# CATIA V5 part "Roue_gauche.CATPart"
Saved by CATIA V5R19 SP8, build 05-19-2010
Part number: Roue_gauche
Bounding box of the stored display mesh (mm): x -1125 to -825, y 1050 to 1950, z -1299.802 to -400.198
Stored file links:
  G:\EU_thinkMotion\CFAO_2010\MMS_groupe2\MMS_groupe2\OK\mmartini\mmartiniCFAO\Roue_gauche.CATPart
  C:\Users\Mathieu Martini\Desktop\CFAO\Animation\CFAO.CATProduct
  G:\EU_thinkMotion\CFAO_2010\MMS_groupe2\MMS_groupe2\OK\mmartini\mmartiniCFAO\Squelette.CATPart
  G:\EU_thinkMotion\CFAO_2010\MMS_groupe2\MMS_groupe2\OK\mmartini\mmartiniCFAO\Roue_droite.CATPart
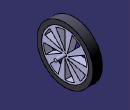
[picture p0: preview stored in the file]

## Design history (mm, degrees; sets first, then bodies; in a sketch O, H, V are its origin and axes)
Parameters
  LENGTH = 150 mm
External parameters (linked from other documents)
  External.diametre_canon = 150 mm
AxisSystem1: origin (0, 0, 0), X (1, 0, 0), Y (0, 1, 0), Z (0, 0, 1)
Set1
  Sketch1 on Plane1, origin (-975, 0, 0), H (0, 1, 0), V (0, 0, 1)
    circle A1 centre (1500, -850) radius 450
    point P1 (1500, -850)
    reference projected point E1 (1500, -850) from Line1
    reference intersected line E2 through (0, -1300) direction (-1, 0) from Plane2
    circle A2 centre (1500, -850) radius 375
    distance A2 A1 = 75 {= External.diametre_canon /2}
    coincidence: P1 E1
    tangency: A1 E2
Set2
  Plane1: linked copy from another document
  Line1 "axe_roue": linked copy from another document
  Plane2 "sol": linked copy from another document
Body1 (main body)
  Pad1: profile Sketch1, direction (-1, 0, 0), length 150 {= External.diametre_canon}
  Sketch2 on Plane1, origin (-975, 0, 0), H (0, 1, 0), V (0, 0, 1)
    projected circle E1 centre (1500, -850) radius 375 from edge [start face of Pad1 | face of Pad1 from Sketch1.A2]
  Pad2: profile Sketch2, direction (-1, 0, 0), length 120 {= External.diametre_canon -External.diametre_canon /5}
  Sketch3 on Plane1, origin (-975, 0, 0), H (0, 1, 0), V (0, 0, 1)
    axis line L1 (1500, -850) -> (1500, -390.9786)
    point P1 (1500, -850)
    reference projected point E1 (1500, -850)
    line L2 (1500, -505) -> (1500, -800)
    point P3 (1500, -505)
    point P4 (1500, -800)
    reference projected circle E2 centre (1500, -850) radius 375
    arc A1 centre (1500, -850) radius 345 from (1500, -505) to (1349.6041, -539.5067) ccw
    line L3 (1500, -800) -> (1349.6041, -539.5067)
    point P6 (1500, -505)
    distance E2 P3 = 30 {= LENGTH /5}
    distance P4 P1 = 50 {= LENGTH /3}
    angle L3 L2 = 30
    vertical: L1 V, L2 V
    coincidence: P1 E1, P4 L1, A1 P3, L1 P6, P3 P6
  Pocket1: profile Sketch3, direction (-1, 0, 0), up to end face of Pad2
  CircPattern1: of Pocket1, instances 8, angular step 45, axis from Line1
  Sketch4 on Plane1, origin (-975, 0, 0), H (0, 1, 0), V (0, 0, 1)
    projected circle E1 centre (1500, -850) radius 375 from edge [face of Pad1 from Sketch1.A2 | end face of Pad1]
  Pocket2: profile Sketch4, direction (-1, 0, 0), length 1.5 {= External.diametre_canon /100}
  Sketch5 on Plane1, origin (-975, 0, 0), H (0, 1, 0), V (0, 0, 1)
    circle A1 centre (1500, -850) radius 25
    point P1 (1500, -850)
    reference projected point E1 (1500, -850) from Line1
    radius A1 = 25 {= External.diametre_canon /6}
    coincidence: P1 E1
  Pad3: profile Sketch5, direction (1, 0, 0), length 150 {= External.diametre_canon}, opposite side up to end face of Pocket2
